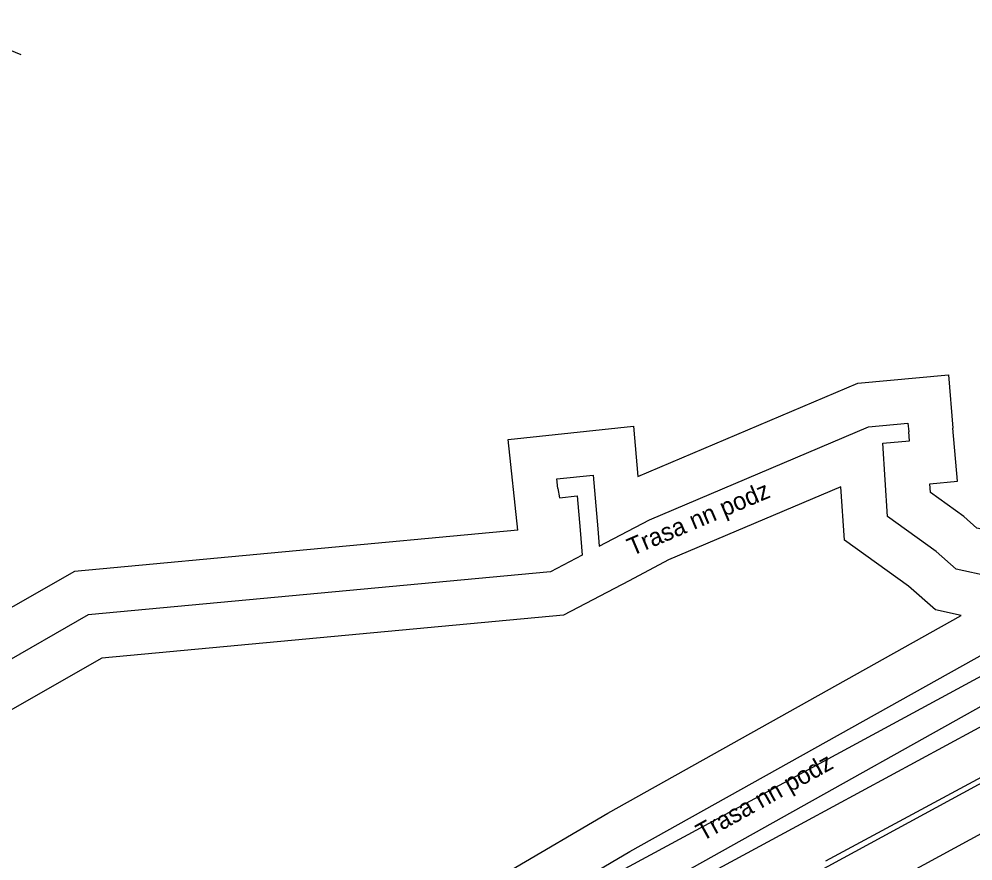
# Model space of a CAD drawing. Extents: x -762993 to -761845, y -975230 to -974501.
# Drawn here: x -762340.27 to -762318.78, y -975022.72 to -975003.77 of the extents above; entities that cross this region are included whole.
import ezdxf

# ---------------------------------------------------------------- set-up
doc = ezdxf.new("R2010")
doc.units = 0
for name, color, linetype in [('IS_CETIN_OP', 7, 'Continuous'), ('IS_CEZ-D_anotace', 7, 'Continuous'), ('IS_CEZ-D_el vedeni NN podzem', 7, 'Continuous'), ('IS_CEZ-D_OP', 7, 'Continuous'), ('IS_GASNET_plyn NTL rad', 7, 'Continuous'), ('IS_GASNET_plyn OP', 7, 'Continuous'), ('IS_T-Mobile_OP', 7, 'Continuous'), ('IS_T-Mobile_podzem optika', 7, 'Continuous')]:
    doc.layers.add(name, color=color, linetype=linetype)

msp = doc.modelspace()

# ---------------------------------------------------------------- linework, layer by layer
at = {"layer": 'IS_CETIN_OP'}
msp.add_lwpolyline([(-762342.909, -974995.85), (-762342.83, -974996.81), (-762342.852, -975003.49), (-762340.229, -975004.565)], dxfattribs=at)
at = {"layer": 'IS_CEZ-D_el vedeni NN podzem'}
for p, q in [((-762328.13, -975014.34), (-762328.098, -975014.543)), ((-762328.098, -975014.543), (-762327.695, -975014.501)), ((-762327.695, -975014.501), (-762327.63, -975015.275)), ((-762327.63, -975015.275), (-762327.582, -975015.836)), ((-762327.582, -975015.836), (-762328.297, -975016.212)), ((-762328.297, -975016.212), (-762338.713, -975017.183)), ((-762338.713, -975017.183), (-762346.71, -975021.736))]:
    msp.add_line(p, q, dxfattribs=at)
for points in [[(-762323.24, -975032.631), (-762327.897, -975023.324), (-762326.508, -975022.51), (-762316.256, -975016.781), (-762313.888, -975015.684), (-762313.128, -975014.455), (-762313.114, -975014.417), (-762312.341, -975012.334), (-762312.311, -975012.253), (-762312.434, -975011.429)], [(-762312.434, -975011.429), (-762312.761, -975011.582), (-762312.716, -975012.195), (-762313.489, -975014.278), (-762314.166, -975015.372), (-762316.424, -975016.419), (-762317.643, -975016.479), (-762319.16, -975016.149), (-762319.611, -975015.754), (-762320.71, -975014.965), (-762320.816, -975013.314), (-762320.212, -975013.263), (-762320.229, -975013.064)], [(-762328.13, -975014.34), (-762328.153, -975014.122), (-762327.338, -975014.034), (-762327.232, -975015.241), (-762327.199, -975015.634), (-762326.068, -975015.04), (-762321.132, -975012.947), (-762320.246, -975012.865), (-762320.229, -975013.064)]]:
    msp.add_lwpolyline(points, dxfattribs=at)
at = {"layer": 'IS_CEZ-D_OP'}
msp.add_line((-762329.037, -975015.277), (-762339.02, -975016.207), dxfattribs=at)
for points in [[(-762312.622, -975010.413), (-762313.809, -975010.968), (-762313.729, -975012.051), (-762314.392, -975013.837), (-762314.859, -975014.591), (-762316.668, -975015.43), (-762317.56, -975015.474), (-762318.695, -975015.227), (-762318.989, -975014.97), (-762319.742, -975014.429), (-762319.755, -975014.228), (-762319.13, -975014.175), (-762319.233, -975012.979)], [(-762329.037, -975015.277), (-762329.252, -975013.235), (-762326.431, -975012.93), (-762326.331, -975014.065), (-762321.379, -975011.966), (-762319.335, -975011.776), (-762319.233, -975012.979)], [(-762321.902, -975033.07), (-762326.584, -975023.714), (-762326.011, -975023.378), (-762315.801, -975017.672), (-762313.195, -975016.465), (-762312.224, -975014.895), (-762312.176, -975014.764), (-762311.559, -975013.102)], [(-762321.755, -975014.297), (-762325.64, -975015.945), (-762326.529, -975016.412)], [(-762319.049, -975017.196), (-762319.625, -975017.071), (-762320.233, -975016.538), (-762321.678, -975015.501), (-762321.755, -975014.297)], [(-762339.02, -975016.207), (-762347.421, -975020.99), (-762351.587, -975027.547), (-762362.679, -975033.548), (-762363.535, -975031.965), (-762364.59, -975032.535)], [(-762326.529, -975016.412), (-762326.529, -975016.412), (-762328.007, -975017.189), (-762338.406, -975018.159), (-762345.999, -975022.482), (-762350.177, -975029.059), (-762363.487, -975036.258), (-762364.343, -975034.675), (-762363.64, -975034.295)], [(-762324.578, -975032.192), (-762329.21, -975022.934), (-762327.005, -975021.642), (-762319.049, -975017.196)]]:
    msp.add_lwpolyline(points, dxfattribs=at)
at = {"layer": 'IS_GASNET_plyn NTL rad'}
msp.add_lwpolyline([(-762382.14, -975056.56), (-762374.12, -975052.41), (-762369.1, -975049.66), (-762366.32, -975048.11), (-762358.1, -975043.65), (-762340.31, -975033.92), (-762334.72, -975030.54), (-762325.49, -975025.85), (-762316.08, -975020.74), (-762311.6, -975018.18), (-762307.32, -975015.61), (-762304.68, -975013.94), (-762304.65, -975013.71), (-762304.31, -975011.18), (-762303.9, -975006.19), (-762303.47, -974998.11), (-762299.684, -974994.021), (-762299.23, -974993.53)], dxfattribs=at)
at = {"layer": 'IS_GASNET_plyn OP'}
msp.add_lwpolyline([(-762382.6, -975055.672), (-762374.59, -975051.527), (-762369.584, -975048.785), (-762366.802, -975047.234), (-762358.578, -975042.772), (-762340.809, -975033.053), (-762335.206, -975029.665), (-762325.955, -975024.965), (-762316.567, -975019.866), (-762312.106, -975017.317), (-762307.845, -975014.759), (-762305.61, -975013.345), (-762305.305, -975011.072), (-762304.898, -975006.122), (-762304.449, -974997.696)], dxfattribs=at)
at = {"layer": 'IS_T-Mobile_OP'}
for p, q in [((-762323.044, -975020.96), (-762318.311, -975018.402)), ((-762322.094, -975022.72), (-762316.609, -975019.756))]:
    msp.add_line(p, q, dxfattribs=at)
msp.add_lwpolyline([(-762334.875, -975027.35), (-762323.044, -975020.96)], dxfattribs=at)
at = {"layer": 'IS_T-Mobile_podzem optika'}
for points in [[(-762322.569, -975021.84), (-762317.46, -975019.079)], [(-762322.569, -975021.84), (-762317.46, -975019.079)], [(-762334.4, -975028.23), (-762322.569, -975021.84)], [(-762334.4, -975028.23), (-762322.569, -975021.84)]]:
    msp.add_lwpolyline(points, dxfattribs=at)

# ---------------------------------------------------------------- texts
at = {"layer": 'IS_CEZ-D_anotace'}
for rotation, p in [(22.9783, (-762326.465, -975015.86)), (29.1972, (-762324.877, -975022.286))]:
    msp.add_text('Trasa nn podz', height=0.4, rotation=rotation, dxfattribs=at).set_placement(p)

doc.saveas('drawing.dxf')
